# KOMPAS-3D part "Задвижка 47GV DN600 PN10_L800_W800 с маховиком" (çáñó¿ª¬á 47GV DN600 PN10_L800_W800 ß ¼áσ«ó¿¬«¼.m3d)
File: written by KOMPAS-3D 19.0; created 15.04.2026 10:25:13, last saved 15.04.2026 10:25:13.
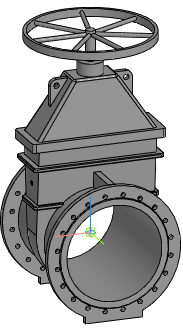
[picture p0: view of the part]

Document properties: Автор: Евгений; Полное имя файла: Z:\3.Личные\kachalov\3d для проектировщиков\2.1 Тип 47GV, 47GV.Z\Задвижка 47GV_DN40-DN600\stp_Задвижка 47GV\Задвижка 47GV DN600 PN10_L800_W800 с маховиком.m3d

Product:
- Part/product: Задвижка 47GV DN600 PN10_L800_W800 с маховиком

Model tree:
1. Операция без истории:1  (labels: Задвижка 47GV DN600 PN10_L800_W800 с маховиком)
